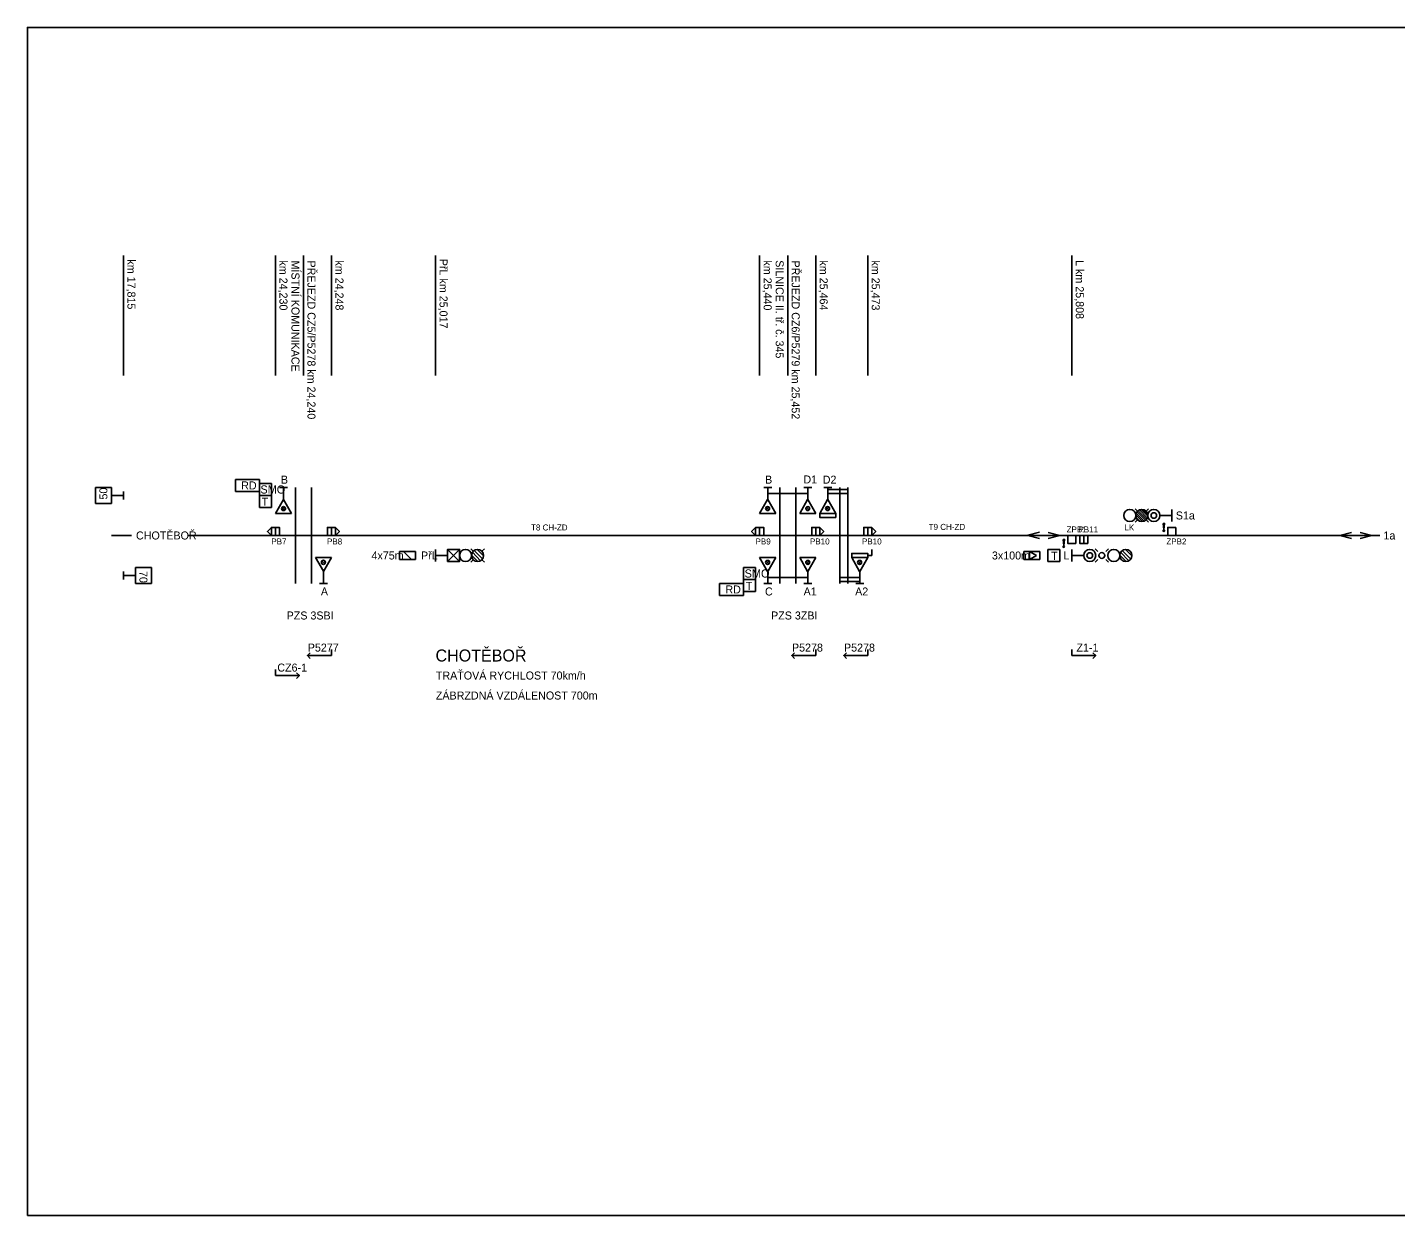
# Model space of a CAD drawing. Extents: x 2343 to 7744, y -5890 to 2050.
# Drawn here: x 5620 to 5961.9, y -5890 to -5593 of the extents above; entities that cross this region are included whole.
import ezdxf

# ---------------------------------------------------------------- set-up
doc = ezdxf.new("R2010")
doc.units = 0
for name, color, linetype in [('LISTY', 7, 'Continuous'), ('NAVRHOVANÉ', 7, 'Continuous'), ('Vrstva 1', 7, 'Continuous'), ('Vrstva 50', 7, 'Continuous'), ('VTO', 7, 'Continuous')]:
    doc.layers.add(name, color=color, linetype=linetype)

# ---------------------------------------------------------------- blocks, each defined once
blk = doc.blocks.new('U3')
at = {"layer": 'Vrstva 1'}
for p, q in [((1, 4), (-1, 4)), ((-1, 4), (-1, 0)), ((1, 0), (1, 4)), ((-1, 1), (1, 3)), ((-1, 0), (1, 0))]:
    blk.add_line(p, q, dxfattribs=at)
blk = doc.blocks.new('NS30')
at = {"layer": 'Vrstva 1'}
for p, q in [((-1.499, 3.001), (0, 1.5)), ((1.499, 3.001), (-1.499, 3.001)), ((-1.499, 0), (0, 1.5)), ((1.499, 0), (-1.499, 0)), ((0, 1.5), (1.499, 3.001)), ((0, 1.5), (1.499, 0))]:
    blk.add_line(p, q, dxfattribs=at)
blk.add_lwpolyline([(-1.499, 3.001), (1.499, 3.001), (1.499, 0), (-1.499, 0)], close=True, dxfattribs=at)
blk = doc.blocks.new('O9')
for p, q in [((1.512, 3.012), (-1.488, 3.012)), ((-1.488, 3.012), (-1.488, 0.012)), ((-1.488, 0.012), (1.512, 0.012)), ((1.512, 0.012), (1.512, 3.012))]:
    blk.add_line(p, q)
blk.add_text('T', height=2).set_placement((-0.664, 0.423))
blk = doc.blocks.new('U7')
at = {"layer": 'Vrstva 1'}
for p, q in [((-1, 4), (-1, 0)), ((1, 4), (-1, 4)), ((1, 0), (1, 4)), ((-1, 0), (1, 0)), ((-0.971, 1.411), (0.029, 3.143)), ((-0.971, 1.411), (1.029, 1.411)), ((0.029, 3.143), (1.029, 1.411))]:
    blk.add_line(p, q, dxfattribs=at)
blk = doc.blocks.new('O1')
for p, q in [((0.01, 0.066), (-2.895, 0.812)), ((0.01, 0.044), (-2.895, -0.702))]:
    blk.add_line(p, q)
blk = doc.blocks.new('SB113')
at = {"layer": 'Vrstva 1'}
for points in [[(10, 0), (-10, 0), (-10, -20), (10, -20)], [(0, 0), (10, 0), (10, -20), (0, -20)]]:
    blk.add_lwpolyline(points, close=True, dxfattribs=at)
blk = doc.blocks.new('NS8')
at = {"layer": 'Vrstva 1'}
for p, q in [((-1.061, 8.561), (-1.7, 9.2)), ((-1.492, 7.372), (0.127, 8.991)), ((-1.424, 7.971), (-0.475, 8.919)), ((-1.391, 6.942), (0.556, 8.889)), ((-1.199, 6.604), (0.896, 8.699)), ((-0.938, 6.335), (1.166, 8.439)), ((-0.61, 6.133), (1.369, 8.112)), ((-0.196, 6.016), (1.486, 7.698)), ((0.363, 6.045), (1.451, 7.133)), ((1.061, 8.561), (1.7, 9.2)), ((-1.061, 6.439), (-1.7, 5.8)), ((1.061, 6.439), (1.7, 5.8)), ((-1.5, 0), (1.5, 0)), ((0, 3), (0, 0))]:
    blk.add_line(p, q, dxfattribs=at)
for centre, radius in [((0, 10.5), 1.5), ((0, 7.5), 1.5), ((0, 4.5), 1.5), ((0, 4.5), 0.7)]:
    blk.add_circle(centre, radius, dxfattribs=at)
blk = doc.blocks.new('P38')
at = {"layer": 'Vrstva 1'}
for p, q in [((0, 15), (0, 0)), ((0, 0), (60, 0))]:
    blk.add_line(p, q, dxfattribs=at)
blk.add_lwpolyline([(52.9, -7.1), (60, 0), (52.9, 7.1)], dxfattribs=at)
blk = doc.blocks.new('O10')
at = {"layer": 'Vrstva 1'}
for p, q in [((3, 3), (-3, 3)), ((-3, 3), (-3, 0)), ((-3, 0), (3, 0)), ((3, 0), (3, 3))]:
    blk.add_line(p, q, dxfattribs=at)
blk.add_text('RD', height=2, dxfattribs=at).set_placement((-1.57, 0.503))
blk = doc.blocks.new('NS44')
at = {"layer": 'Vrstva 1'}
blk.add_lwpolyline([(-3.8, 40), (3.7, 40), (0, 10)], close=True, dxfattribs=at)
blk.add_circle((0, 3.7), 3.75, dxfattribs=at)

msp = doc.modelspace()

# ---------------------------------------------------------------- linework, layer by layer
for p, q in [((5644, -5680), (5644, -5650)), ((5682, -5680), (5682, -5650)), ((5696, -5680), (5696, -5650)), ((5803, -5680), (5803, -5650)), ((5817, -5680), (5817, -5650)), ((5830, -5680), (5830, -5650)), ((5637, -5712), (5637, -5708)), ((5637, -5708), (5641, -5708)), ((5641, -5708), (5641, -5712)), ((5644, -5710), (5641, -5710)), ((5644, -5711), (5644, -5709)), ((5681, -5707), (5678, -5707)), ((5678, -5707), (5678, -5710)), ((5678, -5710), (5681, -5710)), ((5681, -5710), (5681, -5707)), ((5685, -5708), (5683, -5708)), ((5684, -5711.01), (5684, -5708)), ((5687, -5708), (5687, -5732)), ((5691, -5708), (5691, -5732)), ((5808, -5708), (5808, -5732)), ((5812, -5708), (5812, -5732)), ((5823, -5708), (5823, -5732)), ((5825, -5708), (5825, -5732)), ((5641, -5712), (5637, -5712)), ((5683.98, -5711.03), (5682, -5714.52)), ((5683.52, -5713.26), (5684.05, -5713.79)), ((5683.7, -5712.91), (5684.4, -5713.61)), ((5686, -5714.52), (5684.02, -5711.04)), ((5684.13, -5712.8), (5684.5, -5713.18)), ((5686, -5714.52), (5682, -5714.52)), ((5646, -5720), (5641, -5720)), ((5692, -5725.48), (5696, -5725.48)), ((5692, -5725.48), (5693.98, -5728.96)), ((5693.87, -5727.2), (5693.5, -5726.82)), ((5694.3, -5727.09), (5693.6, -5726.39)), ((5694.48, -5726.74), (5693.95, -5726.21)), ((5694.02, -5728.97), (5696, -5725.48)), ((5644, -5731), (5644, -5729)), ((5644, -5730), (5647, -5730)), ((5651, -5728), (5647, -5728)), ((5647, -5728), (5647, -5732)), ((5651, -5732), (5651, -5728)), ((5694, -5728.99), (5694, -5732)), ((5802, -5728), (5799, -5728)), ((5799, -5728), (5799, -5731)), ((5802, -5731), (5802, -5728)), ((5825, -5730.5), (5823, -5730.5)), ((5647, -5732), (5651, -5732)), ((5693, -5732), (5695, -5732)), ((5799, -5731), (5802, -5731))]:
    msp.add_line(p, q)
for points in [[(5820, -5709.5), (5825, -5709.5), (5825, -5708.5), (5820, -5708.5)], [(5822, -5715.5), (5818, -5715.5), (5818, -5714.5), (5822, -5714.5)], [(5830, -5725.5), (5826, -5725.5), (5826, -5724.5), (5830, -5724.5)], [(5823, -5731.5), (5828, -5731.5), (5828, -5730.5), (5823, -5730.5)]]:
    msp.add_lwpolyline(points, close=True)
for centre, major_axis in [((5684.02, -5713.29), (0, 0.502)), ((5693.98, -5726.71), (0, -0.502))]:
    msp.add_ellipse(centre, major_axis=major_axis, ratio=0.996169)
at = {"layer": 'NAVRHOVANÉ'}
for p, q in [((5722, -5680), (5722, -5650)), ((5881, -5680), (5881, -5650)), ((5722, -5723.5), (5722, -5726.5)), ((5731.5, -5724), (5730.8, -5723.3)), ((5733.7, -5725.8), (5731.7, -5723.8)), ((5734, -5725.1), (5732.4, -5723.5)), ((5733.5, -5724), (5734.2, -5723.3)), ((5881, -5723.5), (5881, -5726.5)), ((5887.5, -5724), (5886.8, -5723.3)), ((5889.5, -5724), (5890.2, -5723.3)), ((5895.7, -5725.8), (5893.7, -5723.8)), ((5896, -5725.1), (5894.4, -5723.5)), ((5725, -5725), (5722, -5725)), ((5731.5, -5726), (5730.8, -5726.7)), ((5732.6, -5726.5), (5731, -5724.9)), ((5733.25, -5726.3), (5731.2, -5724.2)), ((5733.5, -5726), (5734.2, -5726.7)), ((5884, -5725), (5881, -5725)), ((5887.5, -5726), (5886.8, -5726.7)), ((5889.5, -5726), (5890.2, -5726.7)), ((5894.6, -5726.5), (5893, -5724.9)), ((5895.25, -5726.3), (5893.2, -5724.2))]:
    msp.add_line(p, q, dxfattribs=at)
for points in [[(5681, -5718), (5680, -5719), (5681, -5720)], [(5697, -5718), (5698, -5719), (5697, -5720)], [(5802, -5718), (5801, -5719), (5802, -5720)], [(5802, -5718), (5801, -5719), (5802, -5720)], [(5818, -5718), (5819, -5719), (5818, -5720)], [(5831, -5718), (5832, -5719), (5831, -5720)], [(5880, -5720), (5882, -5720), (5882, -5722), (5880, -5722)], [(5907, -5718), (5905, -5718), (5905, -5720), (5907, -5720)]]:
    msp.add_lwpolyline(points, close=True, dxfattribs=at)
for centre, radius in [((5729.5, -5725), 1.5), ((5732.5, -5725), 1.5), ((5885.5, -5725), 1.5), ((5891.5, -5725), 1.5), ((5894.5, -5725), 1.5), ((5885.5, -5725), 0.7)]:
    msp.add_circle(centre, radius, dxfattribs=at)
for start, end in [(90, 270), (270, 90)]:
    msp.add_arc((5888.5, -5725), 0.75, start, end, dxfattribs=at)
at = {"layer": 'Vrstva 1'}
for p, q in [((5804, -5708), (5806, -5708)), ((5805, -5711), (5805, -5708)), ((5805, -5709.5), (5810, -5709.5)), ((5815, -5709.5), (5810, -5709.5)), ((5816, -5708), (5814, -5708)), ((5815, -5711), (5815, -5708)), ((5819, -5708), (5821, -5708)), ((5820, -5711), (5820, -5708)), ((5820, -5709.5), (5825, -5709.5)), ((5803, -5714.5), (5804.98, -5711.03)), ((5804.87, -5712.79), (5804.5, -5713.16)), ((5805.3, -5712.89), (5804.6, -5713.59)), ((5805.48, -5713.24), (5804.95, -5713.77)), ((5805.02, -5711.02), (5807, -5714.5)), ((5814.98, -5711.02), (5813, -5714.5)), ((5814.52, -5713.24), (5815.05, -5713.77)), ((5814.7, -5712.89), (5815.4, -5713.59)), ((5817, -5714.5), (5815.02, -5711.03)), ((5815.13, -5712.79), (5815.5, -5713.16)), ((5818, -5714.5), (5819.98, -5711.03)), ((5819.87, -5712.79), (5819.5, -5713.16)), ((5820.3, -5712.89), (5819.6, -5713.59)), ((5820.48, -5713.24), (5819.95, -5713.77)), ((5820.02, -5711.02), (5822, -5714.5)), ((5803, -5714.5), (5807, -5714.5)), ((5817, -5714.5), (5813, -5714.5)), ((5818, -5714.5), (5822, -5714.5)), ((5803, -5725.5), (5807, -5725.5)), ((5803, -5725.5), (5804.98, -5728.98)), ((5804.87, -5727.21), (5804.5, -5726.84)), ((5805.3, -5727.11), (5804.6, -5726.41)), ((5805.48, -5726.76), (5804.95, -5726.23)), ((5805.02, -5728.98), (5807, -5725.5)), ((5814.98, -5728.98), (5813, -5725.5)), ((5817, -5725.5), (5813, -5725.5)), ((5814.52, -5726.76), (5815.05, -5726.23)), ((5814.7, -5727.11), (5815.4, -5726.41)), ((5817, -5725.5), (5815.02, -5728.98)), ((5815.13, -5727.21), (5815.5, -5726.84)), ((5826, -5725.5), (5830, -5725.5)), ((5826, -5725.5), (5827.98, -5728.98)), ((5827.91, -5727.22), (5827.49, -5726.8)), ((5828.32, -5727.1), (5827.61, -5726.39)), ((5828.48, -5726.73), (5827.98, -5726.23)), ((5828.02, -5728.98), (5830, -5725.5)), ((5805, -5729), (5805, -5732)), ((5805, -5730.5), (5810, -5730.5)), ((5815, -5730.5), (5810, -5730.5)), ((5815, -5729), (5815, -5732)), ((5828, -5729), (5828, -5732)), ((5804, -5732), (5806, -5732)), ((5816, -5732), (5814, -5732)), ((5827, -5732), (5829, -5732))]:
    msp.add_line(p, q, dxfattribs=at)
for points in [[(5660, -5720), (5958, -5720)], [(5831, -5723.5), (5831, -5725), (5830, -5725)], [(5826, -5725.5), (5826, -5724.5), (5830, -5724.5), (5830, -5725.5)]]:
    msp.add_lwpolyline(points, dxfattribs=at)
for centre in [(5804.98, -5713.27), (5815.02, -5713.27), (5819.98, -5713.27), (5804.98, -5726.73), (5815.02, -5726.73), (5827.98, -5726.73)]:
    msp.add_circle(centre, 0.5, dxfattribs=at)
at = {"layer": 'Vrstva 50'}
for p, q in [((5689, -5680), (5689, -5650)), ((5810, -5680), (5810, -5650))]:
    msp.add_line(p, q, dxfattribs=at)
msp.add_lwpolyline([(5620, -5890), (6880, -5890), (6880, -5593), (5620, -5593)], close=True, dxfattribs=at)

# ---------------------------------------------------------------- block references
for p in [(5675, -5709), (5796, -5735)]:
    msp.add_blockref('O10', p)
at = {"xscale": 0.1, "yscale": 0.10000000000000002}
for p in [(5682, -5718), (5803, -5718), (5803, -5718)]:
    msp.add_blockref('SB113', p, dxfattribs=at)
at = {"xscale": 0.1, "yscale": -0.10000000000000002, "rotation": 180}
for p in [(5696, -5718), (5817, -5718), (5830, -5718), (5884, -5720)]:
    msp.add_blockref('SB113', p, dxfattribs=at)
at = {"layer": 'LISTY', "xscale": 0.05, "yscale": 0.05000000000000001}
for p in [(5904, -5719), (5879, -5723)]:
    msp.add_blockref('NS44', p, dxfattribs=at)
at = {"layer": 'NAVRHOVANÉ'}
for name, p, rotation in [('NS8', (5906, -5715), 90), ('O1', (5870.01, -5719.91), 180), ('O1', (5948.01, -5719.93), 180), ('NS30', (5728, -5725), 90), ('U3', (5713, -5725), -90.00000000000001)]:
    msp.add_blockref(name, p, dxfattribs=dict(at, rotation=rotation))
for p in [(5877.99, -5720.04), (5955.99, -5720.07)]:
    msp.add_blockref('O1', p, dxfattribs=at)
at = {"layer": 'NAVRHOVANÉ', "yscale": -1, "rotation": 90.00000000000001}
msp.add_blockref('U7', (5869, -5725), dxfattribs=at)
at = {"layer": 'NAVRHOVANÉ', "xscale": 0.1, "yscale": -0.10000000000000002, "rotation": 180}
for p in [(5696, -5750), (5817, -5750), (5830, -5750)]:
    msp.add_blockref('P38', p, dxfattribs=at)
at = {"layer": 'NAVRHOVANÉ', "xscale": 0.1, "yscale": 0.10000000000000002}
for p in [(5881, -5750), (5682, -5755)]:
    msp.add_blockref('P38', p, dxfattribs=at)
at = {"layer": 'VTO', "yscale": -1, "rotation": 180}
for p in [(5679.51, -5713.01), (5800.51, -5734.01)]:
    msp.add_blockref('O9', p, dxfattribs=at)
at = {"layer": 'VTO'}
msp.add_blockref('O9', (5876.49, -5726.51), dxfattribs=at)

# ---------------------------------------------------------------- texts
for s, rotation, p in [('km 17,815', 270, (5645, -5651)), ('km 24,230', 270, (5683, -5651.26)), ('km 24,248', 270, (5697, -5651.26)), ('km 25,440', 270, (5804, -5651.26)), ('SILNICE II. tř. č. 345', 270, (5807, -5651.21)), ('km 25,464', 270, (5818, -5651.26)), ('km 25,473', 270, (5831, -5651.26)), ('50', 90, (5640, -5711.02)), ('70', 270, (5648, -5728.88))]:
    msp.add_text(s, height=2, rotation=rotation).set_placement(p)
for s, height, p in [('B', 2, (5683.35, -5707.05)), ('B', 2, (5804.35, -5707.05)), ('B', 2, (5804.35, -5707.05)), ('D1', 2, (5813.93, -5707)), ('D2', 2, (5818.76, -5707.05)), ('SMO', 2.044, (5678.23, -5709.52)), ('SMO', 2.044, (5799.23, -5730.52)), ('A', 2, (5693.35, -5735)), ('C', 2, (5804.33, -5735)), ('A1', 2, (5813.98, -5735)), ('A2', 2, (5826.86, -5735)), ('PZS 3SBI', 2, (5684.79, -5741)), ('PZS 3ZBI', 2, (5805.85, -5741)), ('CHOTĚBOŘ', 3, (5722, -5751.5)), ('TRAŤOVÁ RYCHLOST 70km/h', 2, (5722.08, -5756)), ('ZÁBRZDNÁ VZDÁLENOST 700m', 2, (5722.08, -5761))]:
    msp.add_text(s, height=height).set_placement(p)
at = {"layer": 'NAVRHOVANÉ'}
for s, p in [('PřL km 25,017', (5723, -5650.86)), ('L km 25,808', (5882, -5651.18))]:
    msp.add_text(s, height=2, rotation=270, dxfattribs=at).set_placement(p)
for s, height, p in [('S1a', 2, (5906.99, -5716)), ('CHOTĚBOŘ', 2, (5647.15, -5721)), ('T8 CH-ZD', 1.5, (5745.86, -5718.75)), ('T9 CH-ZD', 1.5, (5845.23, -5718.6)), ('ZPB1', 1.5, (5879.7, -5719.25)), ('PB11', 1.5, (5882.65, -5719.25)), ('LK', 1.5, (5894.15, -5718.75)), ('PB7', 1.5, (5680.97, -5722.25)), ('PB8', 1.5, (5694.88, -5722.25)), ('PB9', 1.5, (5801.97, -5722.25)), ('PB9', 1.5, (5801.97, -5722.25)), ('PB10', 1.5, (5815.57, -5722.25)), ('PB10', 1.5, (5828.57, -5722.25)), ('ZPB2', 1.5, (5904.63, -5722.25)), ('4x75m', 2, (5706, -5726)), ('PřL', 2, (5718.37, -5726)), ('3x100m', 2, (5861.04, -5726)), ('L', 2, (5878.94, -5726)), ('P5277', 2, (5690.07, -5749.02)), ('P5278', 2, (5811.07, -5749.02)), ('P5278', 2, (5824.07, -5749.02)), ('Z1-1', 2, (5882.17, -5749.02)), ('CZ6-1', 2, (5682.46, -5754.02))]:
    msp.add_text(s, height=height, dxfattribs=at).set_placement(p)
at = {"layer": 'Vrstva 50'}
for s, p in [('MÍSTNÍ KOMUNIKACE', (5686, -5651.28)), ('PŘEJEZD CZ5/P5278 km 24,240', (5690, -5651.27)), ('PŘEJEZD CZ6/P5279 km 25,452', (5811, -5651.27))]:
    msp.add_text(s, height=2, rotation=270, dxfattribs=at).set_placement(p)
msp.add_text('1a', height=2, dxfattribs=at).set_placement((5958.88, -5721))

doc.saveas('drawing.dxf')
